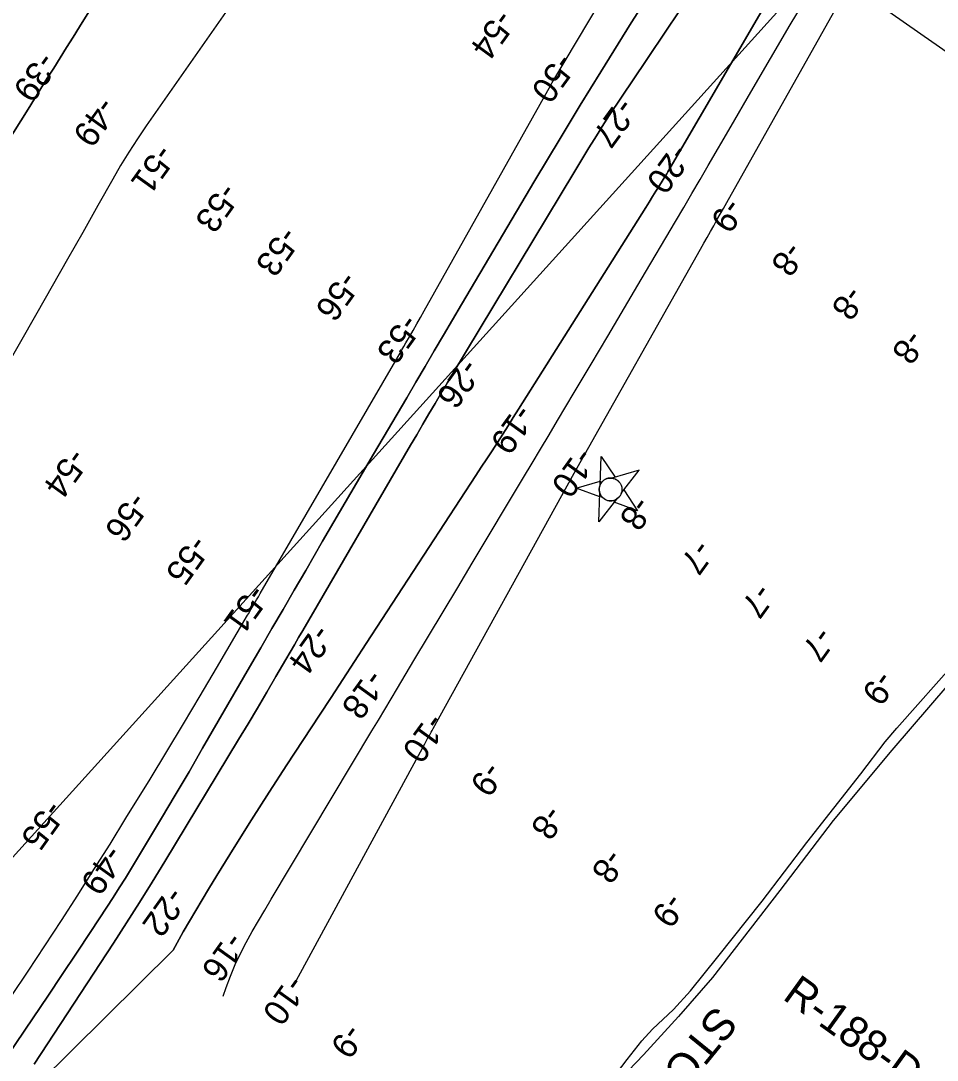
# Model space of a CAD drawing. Extents: x 3879599 to 3900814, y 146526 to 168888.
# Drawn here: x 3891843 to 3893070, y 154874 to 156266 of the extents above; entities that cross this region are included whole.
import ezdxf

# ---------------------------------------------------------------- set-up
doc = ezdxf.new("R2010")
doc.units = 0
for name, color, linetype in [('V-CHAN-NAID', 7, 'Continuous'), ('V-LEVE-TOET', 7, 'Continuous'), ('V-RIVR-JETY', 7, 'Continuous'), ('V-RIVR-RANG', 7, 'Continuous'), ('V-RIVR-RANG-IDEN', 7, 'Continuous'), ('V-TOPO-DPTH', 7, 'Continuous'), ('V-TOPO-MAJR', 7, 'Continuous'), ('V-TOPO-MINR', 7, 'Continuous')]:
    doc.layers.add(name, color=color, linetype=linetype)

msp = doc.modelspace()

# ---------------------------------------------------------------- linework, layer by layer
at = {"layer": 'V-CHAN-NAID'}
for points in [[(3892619.1, 155644.4), (3892620.5, 155682.6), (3892639.2, 155654.9), (3892634.6, 155653.5), (3892634, 155653.6), (3892632.8, 155653.6), (3892631.9, 155653.6), (3892630.9, 155653.4), (3892629.9, 155653.3), (3892629, 155653.1), (3892628.2, 155652.8), (3892627.3, 155652.5), (3892626.4, 155652.1), (3892625.5, 155651.6), (3892624.9, 155651.2), (3892624.2, 155650.7), (3892623.3, 155650), (3892622.7, 155649.5), (3892622, 155648.8), (3892621.4, 155648.2), (3892620.9, 155647.5), (3892620.4, 155646.8), (3892619.9, 155646), (3892619.5, 155645.2)], [(3892647.7, 155633.9), (3892671.4, 155664), (3892634.6, 155653.5), (3892635.7, 155653.4), (3892636.6, 155653.2), (3892637.6, 155652.9), (3892638.6, 155652.6), (3892639.2, 155652.3), (3892640, 155652), (3892640.6, 155651.6), (3892641.3, 155651.2), (3892642, 155650.7), (3892642.7, 155650.2), (3892643.5, 155649.6), (3892644, 155649), (3892644.8, 155648.2), (3892645.4, 155647.4), (3892646, 155646.6), (3892646.4, 155645.8), (3892646.8, 155645), (3892647.2, 155644.2), (3892647.6, 155643.3), (3892647.8, 155642.4), (3892648, 155641.6), (3892648.2, 155640.9), (3892648.3, 155640), (3892648.4, 155639.3), (3892648.4, 155638.2), (3892648.4, 155637.4), (3892648.3, 155636.4), (3892648.1, 155635.4), (3892647.9, 155634.7)], [(3892618.7, 155633.3), (3892618.5, 155628.6), (3892587.1, 155640.1), (3892619.3, 155649.2), (3892619.1, 155644.4), (3892618.8, 155643.6), (3892618.5, 155642.8), (3892618.2, 155641.7), (3892618, 155640.7), (3892617.9, 155639.6), (3892617.8, 155638.6), (3892617.9, 155637.6), (3892617.9, 155636.7), (3892618.1, 155635.7), (3892618.3, 155634.8), (3892618.5, 155633.9)], [(3892640.9, 155625.2), (3892617.2, 155595.1), (3892618.7, 155633.3), (3892619, 155632.5), (3892619.4, 155631.6), (3892619.8, 155630.8), (3892620.4, 155629.9), (3892620.9, 155629.2), (3892621.4, 155628.5), (3892622.1, 155627.7), (3892622.7, 155627.2), (3892623.5, 155626.5), (3892624.4, 155625.8), (3892625.3, 155625.2), (3892626.1, 155624.8), (3892627.1, 155624.3), (3892628.1, 155623.9), (3892629.2, 155623.6), (3892629.9, 155623.4), (3892631, 155623.2), (3892632, 155623.1), (3892633, 155623.1), (3892634, 155623.1), (3892635, 155623.2), (3892636.1, 155623.4), (3892637.2, 155623.6), (3892638.1, 155623.9), (3892639.2, 155624.3), (3892639.9, 155624.7)], [(3892647.7, 155633.9), (3892650.7, 155637.7), (3892669.3, 155609.9), (3892637.9, 155621.4), (3892640.9, 155625.2), (3892641.6, 155625.6), (3892642.5, 155626.3), (3892643.3, 155626.9), (3892644, 155627.7), (3892644.4, 155628.1), (3892644.9, 155628.7), (3892645.5, 155629.3), (3892645.8, 155629.9), (3892646.3, 155630.7), (3892646.7, 155631.3), (3892647.1, 155632.2), (3892647.4, 155632.9), (3892647.6, 155633.4)]]:
    msp.add_lwpolyline(points, close=True, dxfattribs=at)
msp.add_circle((3892633.1, 155638.3), 15.3, dxfattribs=at)
at = {"layer": 'V-LEVE-TOET'}
msp.add_lwpolyline([(3893403.2, 156002.9), (3893217.5, 156130.1), (3893048.4, 156247.9), (3892896.3, 156354.3)], dxfattribs=at)
at = {"layer": 'V-RIVR-JETY'}
for points in [[(3893401.2, 155761.7), (3893383.4, 155735.7), (3893336, 155676), (3893276.6, 155604), (3893212.2, 155535.7), (3893158.9, 155467.2), (3893086, 155378.3), (3893009.8, 155289.4), (3892931, 155195.2), (3892859.8, 155101.4), (3892769.8, 154985), (3892723.9, 154932.9), (3892677.1, 154881.5), (3892656.9, 154860.4), (3892622.6, 154814.1), (3892534.6, 154695.5), (3892451.7, 154594.8), (3892385.6, 154513.6), (3892293.4, 154397.6), (3892219.9, 154301.1), (3892142.7, 154203.1), (3892063.5, 154110.7)], [(3892081.1, 154152.3), (3892145.8, 154229.3), (3892216, 154312.1), (3892259.7, 154367.2), (3892313.4, 154439.5), (3892363.4, 154498.9), (3892416.8, 154568.9), (3892443.3, 154598.8), (3892504.6, 154672), (3892553.8, 154738.6), (3892607.8, 154813.2), (3892655.2, 154875.2), (3892675, 154900.1), (3892689.2, 154915.8), (3892717.3, 154942.3), (3892740.1, 154967.2), (3892776.7, 155012.8), (3892836, 155087.1), (3892895.7, 155165.6), (3892968.1, 155257.8), (3893000.6, 155300.3), (3893016.3, 155318.7), (3893097, 155409.6)]]:
    msp.add_lwpolyline(points, dxfattribs=at)
at = {"layer": 'V-RIVR-RANG'}
msp.add_lwpolyline([(3887950.4, 150855.4), (3895383.9, 159071.9)], dxfattribs=at)
at = {"layer": 'V-TOPO-DPTH'}
msp.add_line((3892047.3, 155021.7), (3891801.2, 154777.8), dxfattribs=at)
for points in [[(3891720.9, 155937.1), (3891853.1, 156147.6), (3891861.7, 156161.4), (3891870.3, 156175.1), (3891878.9, 156188.8), (3891887.6, 156202.5), (3891896.2, 156216.2), (3891904.8, 156229.9), (3891913.4, 156243.6), (3891922, 156257.4), (3892071.1, 156497.7)], [(3891720.9, 155937.1), (3891853.1, 156147.6), (3891861.7, 156161.4), (3891870.3, 156175.1), (3891878.9, 156188.8), (3891887.6, 156202.5), (3891896.2, 156216.2), (3891904.8, 156229.9), (3891913.4, 156243.6), (3891922, 156257.4), (3892071.1, 156497.7)], [(3892916.5, 156417.7), (3892709.7, 156063.4), (3892708.3, 156060.9), (3892707.2, 156059.1), (3892698.5, 156045), (3892693.9, 156037.7), (3892689.4, 156030.4), (3892684.8, 156023.1), (3892680.2, 156015.9), (3892509.9, 155746), (3892502.9, 155734.8), (3892495.8, 155723.6), (3892488.7, 155712.5), (3892481.5, 155701.3), (3892474.4, 155690.2), (3892467.2, 155679.1), (3892460, 155668), (3892452.8, 155656.9), (3892306, 155432), (3892290.4, 155408), (3892274.7, 155384), (3892258.9, 155360), (3892243.2, 155336), (3892199.8, 155269.9), (3892175.9, 155233.1), (3892152.2, 155196.1), (3892128.9, 155159), (3892105.8, 155121.6), (3892094.6, 155103.3), (3892077.6, 155074.9), (3892061, 155046.3), (3892047.3, 155021.7)], [(3892916.5, 156417.7), (3892709.7, 156063.4), (3892708.3, 156060.9), (3892707.2, 156059.1), (3892698.5, 156045), (3892693.9, 156037.7), (3892689.4, 156030.4), (3892684.8, 156023.1), (3892680.2, 156015.9), (3892509.9, 155746), (3892502.9, 155734.8), (3892495.8, 155723.6), (3892488.7, 155712.5), (3892481.5, 155701.3), (3892474.4, 155690.2), (3892467.2, 155679.1), (3892460, 155668), (3892452.8, 155656.9), (3892306, 155432), (3892290.4, 155408), (3892274.7, 155384), (3892258.9, 155360), (3892243.2, 155336), (3892199.8, 155269.9), (3892175.9, 155233.1), (3892152.2, 155196.1), (3892128.9, 155159), (3892105.8, 155121.6), (3892094.6, 155103.3), (3892077.6, 155074.9), (3892061, 155046.3), (3892047.3, 155021.7)], [(3892209.5, 154975.5), (3892384.5, 155298), (3892385.9, 155300.6), (3892387.3, 155303.1), (3892388.6, 155305.7), (3892390, 155308.2), (3892391.4, 155310.7), (3892392.8, 155313.3), (3892394.2, 155315.8), (3892395.6, 155318.3), (3892584.4, 155660.1), (3892753.7, 155960.2), (3892758, 155968), (3892762.4, 155975.8), (3892766.8, 155983.6), (3892771.2, 155991.3), (3892775.6, 155999.1), (3892780, 156006.8), (3892784.3, 156014.6), (3892788.7, 156022.4), (3892976.4, 156356.1)], [(3891801.8, 154845.7), (3891859.9, 154931.1), (3891879.4, 154959.9), (3891898.8, 154988.8), (3891918.1, 155017.7), (3891937.3, 155046.7), (3891958.5, 155079), (3891966.9, 155091.9), (3891975.3, 155105), (3891983.4, 155118.1), (3891991.5, 155131.3), (3892013, 155166.9), (3892031.7, 155198.1), (3892050.3, 155229.2), (3892068.7, 155260.5), (3892086.9, 155291.9), (3892149.8, 155400.5), (3892164.8, 155426.2), (3892179.7, 155452), (3892194.6, 155477.7), (3892209.5, 155503.5), (3892224.9, 155529.9), (3892247.6, 155568.9), (3892270.3, 155607.8), (3892293, 155646.7), (3892315.8, 155685.6), (3892360.1, 155761), (3892372.4, 155782), (3892384.7, 155802.9), (3892397, 155823.9), (3892409.3, 155844.8), (3892433.5, 155886), (3892458, 155927.6), (3892482.5, 155969.1), (3892507.1, 156010.5), (3892531.8, 156051.9), (3892565.4, 156108.1), (3892578.9, 156130.6), (3892592.5, 156152.9), (3892606.2, 156175.2), (3892620, 156197.4), (3892660.8, 156262.8), (3892685.5, 156302.3)], [(3892685.5, 156302.3), (3892660.8, 156262.8), (3892620, 156197.4), (3892606.2, 156175.2), (3892592.5, 156152.9), (3892578.9, 156130.6), (3892565.4, 156108.1), (3892531.8, 156051.9), (3892507.1, 156010.5), (3892482.5, 155969.1), (3892458, 155927.6), (3892433.5, 155886), (3892409.3, 155844.8), (3892397, 155823.9), (3892384.7, 155802.9), (3892372.4, 155782), (3892360.1, 155761), (3892315.8, 155685.6), (3892293, 155646.7), (3892270.3, 155607.8), (3892247.6, 155568.9), (3892224.9, 155529.9), (3892209.5, 155503.5), (3892194.6, 155477.7), (3892179.7, 155452), (3892164.8, 155426.2), (3892149.8, 155400.5), (3892086.9, 155291.9), (3892068.7, 155260.5), (3892050.3, 155229.2), (3892031.7, 155198.1), (3892013, 155166.9), (3891991.5, 155131.3), (3891983.4, 155118.1), (3891975.3, 155105), (3891966.9, 155091.9), (3891958.5, 155079), (3891937.3, 155046.7), (3891918.1, 155017.7), (3891898.8, 154988.8), (3891879.4, 154959.9), (3891859.9, 154931.1), (3891801.8, 154845.7)], [(3891861.1, 154868.8), (3891967.4, 155031.1), (3891985, 155058.2), (3892002.3, 155085.4), (3892019.4, 155112.8), (3892036.2, 155140.4), (3892135, 155303.6), (3892147.7, 155324.6), (3892160.2, 155345.7), (3892172.7, 155366.8), (3892185.1, 155387.9), (3892198.4, 155410.9), (3892204.1, 155420.6), (3892209.7, 155430.3), (3892215.4, 155440), (3892221, 155449.7), (3892365.4, 155697.7), (3892373.5, 155711.6), (3892381.7, 155725.6), (3892389.9, 155739.5), (3892398.2, 155753.4), (3892407.3, 155768.8), (3892411, 155775.1), (3892414.7, 155781.3), (3892418.4, 155787.5), (3892422.1, 155793.7), (3892583.8, 156062.3), (3892590.6, 156073.5), (3892597.3, 156084.6), (3892604.2, 156095.7), (3892611.1, 156106.8), (3892618.6, 156119), (3892621.8, 156124), (3892624.9, 156128.9), (3892628.2, 156133.9), (3892631.4, 156138.8), (3892680.7, 156212.6), (3892708.7, 156254.4), (3892736.6, 156296.2)], [(3892736.6, 156296.2), (3892708.7, 156254.4), (3892680.7, 156212.6), (3892631.4, 156138.8), (3892628.2, 156133.9), (3892624.9, 156128.9), (3892621.8, 156124), (3892618.6, 156119), (3892611.1, 156106.8), (3892604.2, 156095.7), (3892597.3, 156084.6), (3892590.6, 156073.5), (3892583.8, 156062.3), (3892422.1, 155793.7), (3892418.4, 155787.5), (3892414.7, 155781.3), (3892411, 155775.1), (3892407.3, 155768.8), (3892398.2, 155753.4), (3892389.9, 155739.5), (3892381.7, 155725.6), (3892373.5, 155711.6), (3892365.4, 155697.7), (3892221, 155449.7), (3892215.4, 155440), (3892209.7, 155430.3), (3892204.1, 155420.6), (3892198.4, 155410.9), (3892185.1, 155387.9), (3892172.7, 155366.8), (3892160.2, 155345.7), (3892147.7, 155324.6), (3892135, 155303.6), (3892036.2, 155140.4), (3892019.4, 155112.8), (3892002.3, 155085.4), (3891985, 155058.2), (3891967.4, 155031.1), (3891861.1, 154868.8)]]:
    msp.add_lwpolyline(points, dxfattribs=at)
at = {"layer": 'V-TOPO-MAJR'}
for points in [[(3891830.7, 154959.7), (3891853.2, 154993.4), (3891875.5, 155027.2), (3891897.7, 155061.1), (3891919.6, 155095.2), (3891941.4, 155129.4), (3891962.9, 155163.7), (3891984.2, 155198.2), (3892016.5, 155250.7), (3892039, 155287.7), (3892061.4, 155324.7), (3892083.6, 155361.9), (3892105.6, 155399.2), (3892147.1, 155470), (3892148.2, 155471.9), (3892150.5, 155475.8), (3892151.6, 155477.8), (3892154.2, 155482.2), (3892156.6, 155486.4), (3892159, 155490.6), (3892161.5, 155494.7), (3892163.9, 155498.9), (3892348.6, 155816.2), (3892351.2, 155820.7), (3892353.8, 155825.3), (3892356.4, 155829.8), (3892359.1, 155834.4), (3892363.8, 155842.6), (3892368.7, 155851.3), (3892373.7, 155860), (3892378.6, 155868.7), (3892383.5, 155877.4), (3892552.9, 156179.6), (3892554.9, 156183.2), (3892557, 156186.8), (3892759.6, 156526.9)], [(3892170.4, 156352.9), (3892011.3, 156125), (3891999.5, 156107.6), (3891988, 156090), (3891977.1, 156072), (3891966.5, 156053.9), (3891946.6, 156018.4), (3891926.3, 155982.4), (3891906, 155946.4), (3891885.5, 155910.4), (3891865.1, 155874.5), (3891816, 155788.4)]]:
    msp.add_lwpolyline(points, dxfattribs=at)
at = {"layer": 'V-TOPO-MINR'}
for points in [[(3892071.1, 156497.7), (3891922, 156257.4), (3891913.4, 156243.6), (3891904.8, 156229.9), (3891896.2, 156216.2), (3891887.6, 156202.5), (3891878.9, 156188.8), (3891870.3, 156175.1), (3891861.7, 156161.4), (3891853.1, 156147.6), (3891720.9, 155937.1)], [(3892047.3, 155021.7), (3892061, 155046.3), (3892077.6, 155074.9), (3892094.6, 155103.3), (3892105.8, 155121.6), (3892128.9, 155159), (3892152.2, 155196.1), (3892175.9, 155233.1), (3892199.8, 155269.9), (3892243.2, 155336), (3892258.9, 155360), (3892274.7, 155384), (3892290.4, 155408), (3892306, 155432), (3892452.8, 155656.9), (3892460, 155668), (3892467.2, 155679.1), (3892474.4, 155690.2), (3892481.5, 155701.3), (3892488.7, 155712.5), (3892495.8, 155723.6), (3892502.9, 155734.8), (3892509.9, 155746), (3892680.2, 156015.9), (3892684.8, 156023.1), (3892689.4, 156030.4), (3892693.9, 156037.7), (3892698.5, 156045), (3892707.2, 156059.1), (3892708.3, 156060.9), (3892709.7, 156063.4), (3892916.5, 156417.7)], [(3892209.5, 154975.5), (3892384.5, 155298), (3892385.9, 155300.6), (3892387.3, 155303.1), (3892388.6, 155305.7), (3892390, 155308.2), (3892391.4, 155310.7), (3892392.8, 155313.3), (3892394.2, 155315.8), (3892395.6, 155318.3), (3892584.4, 155660.1), (3892753.7, 155960.2), (3892758, 155968), (3892762.4, 155975.8), (3892766.8, 155983.6), (3892771.2, 155991.3), (3892775.6, 155999.1), (3892780, 156006.8), (3892784.3, 156014.6), (3892788.7, 156022.4), (3892976.4, 156356.1)], [(3891801.8, 154845.7), (3891859.9, 154931.1), (3891879.4, 154959.9), (3891898.8, 154988.8), (3891918.1, 155017.7), (3891937.3, 155046.7), (3891958.5, 155079), (3891966.9, 155091.9), (3891975.3, 155105), (3891983.4, 155118.1), (3891991.5, 155131.3), (3892013, 155166.9), (3892031.7, 155198.1), (3892050.3, 155229.2), (3892068.7, 155260.5), (3892086.9, 155291.9), (3892149.8, 155400.5), (3892164.8, 155426.2), (3892179.7, 155452), (3892194.6, 155477.7), (3892209.5, 155503.5), (3892224.9, 155529.9), (3892247.6, 155568.9), (3892270.3, 155607.8), (3892293, 155646.7), (3892315.8, 155685.6), (3892360.1, 155761), (3892372.4, 155782), (3892384.7, 155802.9), (3892397, 155823.9), (3892409.3, 155844.8), (3892433.5, 155886), (3892458, 155927.6), (3892482.5, 155969.1), (3892507.1, 156010.5), (3892531.8, 156051.9), (3892565.4, 156108.1), (3892578.9, 156130.6), (3892592.5, 156152.9), (3892606.2, 156175.2), (3892620, 156197.4), (3892660.8, 156262.8), (3892685.5, 156302.3)], [(3892114.5, 154959.8), (3892118.4, 154971.4), (3892124.1, 154987), (3892130.4, 155002.3), (3892137.5, 155017.3), (3892145.2, 155032), (3892153.4, 155046.5), (3892161.7, 155061), (3892170.1, 155075.3), (3892178.5, 155089.7), (3892313.6, 155315.3), (3892322.2, 155329.6), (3892330.7, 155343.9), (3892339.3, 155358.2), (3892347.8, 155372.4), (3892369.8, 155409.2), (3892389.3, 155441.8), (3892408.9, 155474.5), (3892428.4, 155507.1), (3892448, 155539.8), (3892516.5, 155654.2), (3892527.9, 155673.3), (3892539.3, 155692.4), (3892550.7, 155711.6), (3892562.1, 155730.7), (3892584.4, 155768.1), (3892606.9, 155805.9), (3892629.3, 155843.7), (3892651.8, 155881.6), (3892674.2, 155919.5), (3892720.1, 155997), (3892731.1, 156015.7), (3892742.1, 156034.4), (3892753, 156053.2), (3892763.9, 156072), (3892794.5, 156124.8), (3892820.8, 156170), (3892847.1, 156215.1), (3892873.7, 156260.2), (3892900.4, 156305.1)], [(3891861.1, 154868.8), (3891967.4, 155031.1), (3891985, 155058.2), (3892002.3, 155085.4), (3892019.4, 155112.8), (3892036.2, 155140.4), (3892135, 155303.6), (3892147.7, 155324.6), (3892160.2, 155345.7), (3892172.7, 155366.8), (3892185.1, 155387.9), (3892198.4, 155410.9), (3892204.1, 155420.6), (3892209.7, 155430.3), (3892215.4, 155440), (3892221, 155449.7), (3892365.4, 155697.7), (3892373.5, 155711.6), (3892381.7, 155725.6), (3892389.9, 155739.5), (3892398.2, 155753.4), (3892407.3, 155768.8), (3892411, 155775.1), (3892414.7, 155781.3), (3892418.4, 155787.5), (3892422.1, 155793.7), (3892583.8, 156062.3), (3892590.6, 156073.5), (3892597.3, 156084.6), (3892604.2, 156095.7), (3892611.1, 156106.8), (3892618.6, 156119), (3892621.8, 156124), (3892624.9, 156128.9), (3892628.2, 156133.9), (3892631.4, 156138.8), (3892680.7, 156212.6), (3892708.7, 156254.4), (3892736.6, 156296.2)]]:
    msp.add_lwpolyline(points, dxfattribs=at)

# ---------------------------------------------------------------- texts
at = {"layer": 'V-RIVR-JETY'}
msp.add_text('STONE', height=42, rotation=230.9182, dxfattribs=at).set_placement((3892773.5, 154949.3))
at = {"layer": 'V-RIVR-RANG'}
for s, rotation, p in [('-54', 233.9387, (3892482.2, 156282.8)), ('-39', 234.3277, (3891869.4, 156226.1)), ('-50', 233.9387, (3892563.4, 156224.7)), ('-49', 234.3277, (3891949.4, 156166)), ('-27', 233.9387, (3892644.8, 156164.8)), ('-51', 234.3277, (3892027, 156102.6)), ('-20', 233.7983, (3892717.8, 156103)), ('-53', 234.3277, (3892113.1, 156051)), ('-9', 233.7983, (3892788.9, 156030.8)), ('-53', 234.3277, (3892194.1, 155992.4)), ('-8', 233.7983, (3892869.9, 155972.2)), ('-56', 234.3277, (3892274.2, 155932.5)), ('-8', 233.7983, (3892950.8, 155913.4)), ('-53', 234.3277, (3892356.1, 155875.2)), ('-8', 233.7983, (3893031.6, 155854.5)), ('-26', 234.3277, (3892436.5, 155815.7)), ('-19', 234.1883, (3892508.4, 155754.3)), ('-54', 234.2084, (3891910.5, 155695.8)), ('-10', 234.1883, (3892590, 155696.4)), ('-56', 234.2084, (3891992.2, 155637)), ('-8', 234.1883, (3892666.7, 155631.8)), ('-55', 234.2084, (3892073.6, 155579.2)), ('-7', 234.1883, (3892747.7, 155573.2)), ('-7', 234.1883, (3892829, 155514.9)), ('-51', 234.2084, (3892151.6, 155513.3)), ('-24', 234.2084, (3892238.1, 155459.9)), ('-7', 234.1883, (3892910.2, 155456.6)), ('-18', 234.0683, (3892309.3, 155399.5)), ('-9', 234.1883, (3892991.4, 155398.2)), ('-10', 234.0683, (3892390.5, 155341.2)), ('-9', 234.0683, (3892466.8, 155276.1)), ('-55', 234.4529, (3891879.6, 155224.5)), ('-8', 234.0683, (3892548.1, 155217.9)), ('-49', 234.4529, (3891959.5, 155164.4)), ('-8', 234.0683, (3892629.3, 155159.4)), ('-22', 234.4529, (3892042.1, 155108.5)), ('-9', 234.0683, (3892710.1, 155100.6)), ('-16', 234.3083, (3892121.7, 155048)), ('-10', 234.3083, (3892203.2, 154990.1)), ('-9', 234.3083, (3892279.8, 154925.4))]:
    msp.add_text(s, height=33.5, rotation=rotation, dxfattribs=at).set_placement(p)
at = {"layer": 'V-RIVR-RANG-IDEN'}
msp.add_text('R-188-D', height=41.5, rotation=324.2083, dxfattribs=at).set_placement((3892862, 154956.9))

doc.saveas('drawing.dxf')
